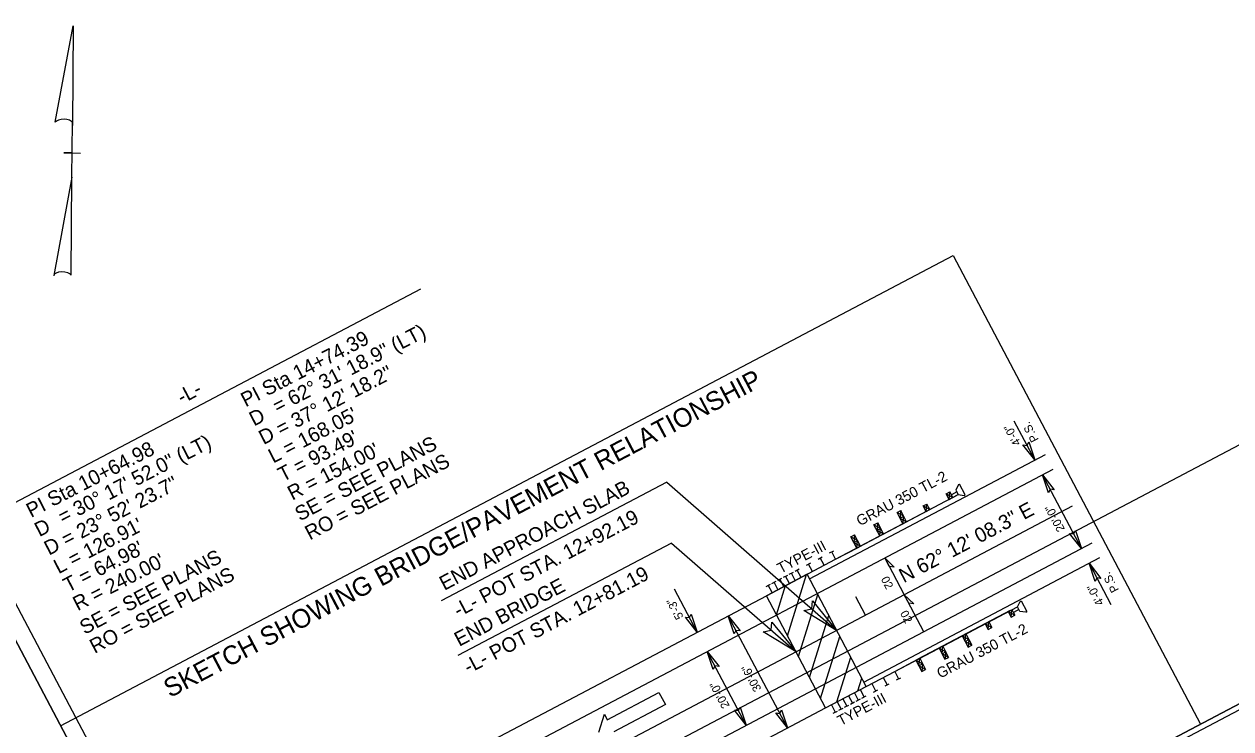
# Model space of a CAD drawing. Extents: x 1380651 to 1383136, y 594581 to 596344.
# Drawn here: x 1381162 to 1381741, y 594902 to 595240 of the extents above; entities that cross this region are included whole.
import ezdxf

# ---------------------------------------------------------------- set-up
doc = ezdxf.new("R2010")
doc.units = 0
for name, color, linetype in [('Default', 7, 'Continuous'), ('Prop Approach Slab', 7, 'Continuous'), ('Prop Approach Slab Hatching', 7, 'Continuous'), ('Prop DGN Element Guardrail', 7, 'Continuous'), ('Prop Dimension', 7, 'Continuous'), ('Prop EOT', 7, 'Continuous'), ('Prop Guardrail', 7, 'Continuous'), ('Prop Guardrail Anchor Unit CELL', 7, 'Continuous'), ('Prop Horizontal Alignment', 7, 'Continuous'), ('Prop Horizontal Alignment Curve and Spiral Data', 7, 'Continuous'), ('Prop Horizontal Alignment Direction Label', 7, 'Continuous'), ('Prop Horizontal Alignment Station Label', 7, 'Continuous'), ('Prop Horizontal Alignment Tick Small', 7, 'Continuous'), ('Prop Lane Arrow CELL', 7, 'Continuous'), ('Prop North Arrow for Plan Sheets CELL', 7, 'Continuous'), ('Prop Paved Shoulder', 7, 'Continuous'), ('Prop Roadway Bridge', 7, 'Continuous'), ('Prop Structure Anchor Unit CELL', 7, 'Continuous'), ('Prop Superelevation  Arrow CELL', 7, 'Continuous'), ('Prop Superelevation Label', 7, 'Continuous'), ('Prop Terminator CELL', 7, 'Continuous'), ('Sheet Block Revision CELL', 7, 'Continuous'), ('Sheet Clip Boundary CELL', 7, 'Continuous'), ('Sheet Layout Plan Border', 7, 'Continuous'), ('Sheet Plan CELL', 7, 'Continuous'), ('Sheet Plot Border Inside CELL', 7, 'Continuous')]:
    doc.layers.add(name, color=color, linetype=linetype)

msp = doc.modelspace()

# ---------------------------------------------------------------- linework, layer by layer
at = {"layer": 'Prop Approach Slab'}
for p, q in [((1381537.57, 594976.49), (1381518.11, 594966.23)), ((1381565.94, 594922.68), (1381537.57, 594976.49)), ((1381546.48, 594912.42), (1381518.11, 594966.23)), ((1381546.48, 594912.42), (1381565.94, 594922.68))]:
    msp.add_line(p, q, dxfattribs=at)
at = {"layer": 'Prop Approach Slab Hatching'}
for p, q in [((1381528.24, 594947.02), (1381537.32, 594976.37)), ((1381522.96, 594957.03), (1381527.32, 594971.09)), ((1381533.51, 594937.01), (1381542.71, 594966.73)), ((1381538.79, 594927), (1381547.99, 594956.72)), ((1381544.07, 594916.99), (1381553.27, 594946.71)), ((1381551.91, 594915.29), (1381558.54, 594936.71)), ((1381561.92, 594920.56), (1381563.82, 594926.7))]:
    msp.add_line(p, q, dxfattribs=at)
at = {"layer": 'Prop DGN Element Guardrail'}
for p, q in [((1381551.28, 594983.72), (1381610.04, 595014.73)), ((1381518.11, 594966.23), (1381551.28, 594983.72)), ((1381579.65, 594929.91), (1381638.44, 594960.87)), ((1381546.48, 594912.42), (1381579.65, 594929.91))]:
    msp.add_line(p, q, dxfattribs=at)
at = {"layer": 'Prop Dimension'}
for p, q in [((1381646.73, 595031.31), (1381636.9, 595049.96)), ((1381669.12, 594988.85), (1381650.46, 595024.24)), ((1381672.85, 594981.77), (1381683.3, 594961.94)), ((1381484.88, 594948.72), (1381474.02, 594969.33)), ((1381528.21, 594902.79), (1381499.84, 594956.6)), ((1381508.39, 594904.12), (1381489.74, 594939.5))]:
    msp.add_line(p, q, dxfattribs=at)
at = {"layer": 'Prop EOT'}
for p, q in [((1381247.91, 594812.01), (1381655.59, 595026.94)), ((1381266.56, 594776.63), (1381674.25, 594991.56))]:
    msp.add_line(p, q, dxfattribs=at)
at = {"layer": 'Prop Guardrail'}
for p, q in [((1381551.28, 594983.72), (1381562.34, 594989.55)), ((1381579.65, 594929.91), (1381590.71, 594935.74))]:
    msp.add_line(p, q, dxfattribs=at)
at = {"layer": 'Prop Guardrail Anchor Unit CELL'}
for p, q in [((1381610.18, 595019.51), (1381608.9, 595016.9)), ((1381610.18, 595019.51), (1381610.72, 595019.79)), ((1381613.47, 595014.6), (1381610.72, 595019.79)), ((1381606.57, 595012.87), (1381562.34, 594989.55)), ((1381604.26, 595015.09), (1381606.03, 595016.02)), ((1381605.68, 595012.4), (1381604.26, 595015.09)), ((1381604.27, 595015.09), (1381607.45, 595013.34)), ((1381605.68, 595012.4), (1381606.04, 595016.02)), ((1381605.68, 595012.4), (1381607.45, 595013.34)), ((1381607.45, 595013.34), (1381606.03, 595016.02)), ((1381609.37, 595016), (1381606.77, 595014.63)), ((1381607.44, 595013.35), (1381610.04, 595014.73)), ((1381608.9, 595016.9), (1381610.04, 595014.73)), ((1381610.04, 595014.73), (1381612.92, 595014.31)), ((1381612.92, 595014.31), (1381613.47, 595014.6)), ((1381580.73, 595006.11), (1381582.5, 595007.05)), ((1381582.5, 595007.05), (1381582.15, 595003.43)), ((1381585.34, 595001.68), (1381582.5, 595007.05)), ((1381593.21, 595009.26), (1381594.98, 595010.19)), ((1381594.62, 595006.57), (1381593.21, 595009.26)), ((1381593.21, 595009.26), (1381596.39, 595007.51)), ((1381594.62, 595006.57), (1381594.98, 595010.19)), ((1381594.62, 595006.57), (1381596.39, 595007.51)), ((1381596.39, 595007.51), (1381594.98, 595010.19)), ((1381569.68, 595000.29), (1381571.45, 595001.22)), ((1381571.45, 595001.22), (1381571.09, 594997.6)), ((1381574.28, 594995.85), (1381571.45, 595001.22)), ((1381583.57, 595000.74), (1381580.73, 595006.11)), ((1381583.92, 595004.36), (1381580.73, 595006.11)), ((1381582.15, 595003.43), (1381583.92, 595004.36)), ((1381582.15, 595003.43), (1381585.34, 595001.68)), ((1381583.57, 595000.74), (1381583.92, 595004.36)), ((1381583.57, 595000.74), (1381585.34, 595001.68)), ((1381558.62, 594994.46), (1381560.39, 594995.39)), ((1381560.39, 594995.39), (1381560.04, 594991.77)), ((1381563.22, 594990.02), (1381560.39, 594995.39)), ((1381572.51, 594994.92), (1381569.68, 595000.29)), ((1381572.86, 594998.53), (1381569.68, 595000.29)), ((1381571.09, 594997.6), (1381572.86, 594998.53)), ((1381571.09, 594997.6), (1381574.28, 594995.85)), ((1381572.51, 594994.92), (1381572.86, 594998.53)), ((1381572.51, 594994.92), (1381574.28, 594995.85)), ((1381561.45, 594989.09), (1381558.62, 594994.46)), ((1381561.81, 594992.71), (1381558.62, 594994.46)), ((1381560.04, 594991.77), (1381561.81, 594992.71)), ((1381560.04, 594991.77), (1381563.22, 594990.02)), ((1381561.45, 594989.09), (1381561.81, 594992.71)), ((1381561.45, 594989.09), (1381563.22, 594990.02)), ((1381635.83, 594959.51), (1381638.44, 594960.87)), ((1381639.57, 594958.71), (1381638.43, 594960.87)), ((1381638.44, 594960.87), (1381639.72, 594963.49)), ((1381639.72, 594963.49), (1381640.26, 594963.78)), ((1381640.26, 594963.78), (1381643, 594958.57)), ((1381634.94, 594959.06), (1381590.71, 594935.74)), ((1381634.05, 594958.59), (1381635.82, 594959.52)), ((1381634.05, 594958.59), (1381635.47, 594955.9)), ((1381634.05, 594958.59), (1381637.24, 594956.84)), ((1381635.47, 594955.9), (1381635.82, 594959.52)), ((1381635.47, 594955.9), (1381637.24, 594956.84)), ((1381635.82, 594959.52), (1381637.24, 594956.84)), ((1381639.1, 594959.6), (1381636.5, 594958.23)), ((1381642.45, 594958.28), (1381639.57, 594958.71)), ((1381642.45, 594958.28), (1381643, 594958.57)), ((1381622.99, 594952.76), (1381624.76, 594953.69)), ((1381622.99, 594952.76), (1381624.41, 594950.07)), ((1381622.99, 594952.76), (1381626.18, 594951.01)), ((1381624.41, 594950.07), (1381624.76, 594953.69)), ((1381624.41, 594950.07), (1381626.18, 594951.01)), ((1381624.76, 594953.69), (1381626.18, 594951.01)), ((1381611.94, 594946.93), (1381613.71, 594947.86)), ((1381611.94, 594946.93), (1381614.77, 594941.56)), ((1381611.94, 594946.93), (1381615.12, 594945.18)), ((1381613.35, 594944.25), (1381613.71, 594947.86)), ((1381613.35, 594944.25), (1381615.12, 594945.18)), ((1381616.54, 594942.49), (1381613.35, 594944.25)), ((1381613.71, 594947.86), (1381616.54, 594942.49)), ((1381615.12, 594945.18), (1381614.77, 594941.56)), ((1381600.88, 594941.1), (1381602.65, 594942.03)), ((1381600.88, 594941.1), (1381603.71, 594935.73)), ((1381600.88, 594941.1), (1381604.06, 594939.35)), ((1381602.3, 594938.42), (1381602.65, 594942.03)), ((1381602.3, 594938.42), (1381604.06, 594939.35)), ((1381605.48, 594936.66), (1381602.3, 594938.42)), ((1381602.65, 594942.03), (1381605.48, 594936.66)), ((1381604.06, 594939.35), (1381603.71, 594935.73)), ((1381614.77, 594941.56), (1381616.54, 594942.49)), ((1381589.82, 594935.27), (1381591.59, 594936.21)), ((1381589.82, 594935.27), (1381592.65, 594929.9)), ((1381589.82, 594935.27), (1381593.01, 594933.52)), ((1381591.24, 594932.59), (1381591.59, 594936.21)), ((1381591.24, 594932.59), (1381593.01, 594933.52)), ((1381594.42, 594930.83), (1381591.24, 594932.59)), ((1381591.59, 594936.21), (1381594.42, 594930.83)), ((1381593.01, 594933.52), (1381592.65, 594929.9)), ((1381603.71, 594935.73), (1381605.48, 594936.66)), ((1381592.65, 594929.9), (1381594.42, 594930.83))]:
    msp.add_line(p, q, dxfattribs=at)
at = {"layer": 'Prop Horizontal Alignment'}
msp.add_line((1381259.34, 594795.43), (1381664.92, 595009.25), dxfattribs=at)
at = {"layer": 'Prop Horizontal Alignment Curve and Spiral Data'}
msp.add_line((1381154.62, 595009.14), (1381352.46, 595113.44), dxfattribs=at)
at = {"layer": 'Prop Horizontal Alignment Station Label'}
for p, q in [((1381470.29, 595020.72), (1381362.17, 594963.72)), ((1381470.29, 595020.72), (1381551.75, 594949.59)), ((1381472.59, 594991.46), (1381370.22, 594937.49)), ((1381472.59, 594991.46), (1381532.29, 594939.33))]:
    msp.add_line(p, q, dxfattribs=at)
at = {"layer": 'Prop Horizontal Alignment Tick Small'}
msp.add_line((1381565.57, 594956.87), (1381560.91, 594965.72), dxfattribs=at)
at = {"layer": 'Prop Lane Arrow CELL'}
for p, q in [((1381441.81, 594906.77), (1381466.58, 594919.83)), ((1381466.58, 594919.83), (1381469.66, 594913.99)), ((1381469.66, 594913.99), (1381444.89, 594900.93)), ((1381437.82, 594900.82), (1381440.41, 594909.42)), ((1381440.41, 594909.42), (1381441.81, 594906.77))]:
    msp.add_line(p, q, dxfattribs=at)
at = {"layer": 'Prop North Arrow for Plan Sheets CELL'}
for p, q in [((1381177.14, 595193.28), (1381185.75, 595239.55)), ((1381185.8, 595239.55), (1381185.38, 595191.76)), ((1381185.8, 595239.55), (1381185.75, 595239.55)), ((1381185.8, 595239.55), (1381185.75, 595239.55)), ((1381185.16, 595166.96), (1381185.39, 595193.16)), ((1381185.38, 595191.76), (1381185.39, 595193.11)), ((1381181.26, 595178.59), (1381181.21, 595178.59)), ((1381184.81, 595178.56), (1381181.26, 595178.59)), ((1381181.31, 595178.59), (1381189.31, 595178.52)), ((1381185.16, 595166.96), (1381176.39, 595119.78)), ((1381184.79, 595119.91), (1381185.16, 595166.96))]:
    msp.add_line(p, q, dxfattribs=at)
for centre, start_param, end_param in [((1381181.27, 595192.75), 0.216388, 2.908219), ((1381180.62, 595119.58), 0.201328, 3.141593)]:
    msp.add_ellipse(centre, major_axis=(4.23, -0.07), ratio=0.461098, start_param=start_param, end_param=end_param, dxfattribs=at)
at = {"layer": 'Prop Paved Shoulder'}
for p, q in [((1381538.69, 594974.36), (1381651.86, 595034.02)), ((1381564.81, 594924.82), (1381677.98, 594984.48))]:
    msp.add_line(p, q, dxfattribs=at)
at = {"layer": 'Prop Roadway Bridge'}
for p, q in [((1381345.82, 594875.41), (1381518.11, 594966.23)), ((1381374.19, 594821.59), (1381546.48, 594912.42))]:
    msp.add_line(p, q, dxfattribs=at)
at = {"layer": 'Prop Structure Anchor Unit CELL'}
for p, q in [((1381518.11, 594966.23), (1381551.28, 594983.72)), ((1381542.87, 594983.81), (1381544.9, 594984.88)), ((1381545.75, 594980.81), (1381543.88, 594984.35)), ((1381548.4, 594986.73), (1381550.43, 594987.8)), ((1381551.28, 594983.72), (1381549.41, 594987.26)), ((1381529.05, 594976.53), (1381531.08, 594977.59)), ((1381531.81, 594977.98), (1381533.84, 594979.05)), ((1381534.69, 594974.98), (1381532.83, 594978.52)), ((1381537.34, 594980.9), (1381539.37, 594981.97)), ((1381540.22, 594977.89), (1381538.36, 594981.43)), ((1381517.99, 594970.7), (1381520.02, 594971.76)), ((1381520.76, 594972.15), (1381522.78, 594973.22)), ((1381523.63, 594969.15), (1381521.77, 594972.69)), ((1381523.52, 594973.61), (1381525.55, 594974.68)), ((1381526.4, 594970.61), (1381524.53, 594974.15)), ((1381526.28, 594975.07), (1381528.31, 594976.14)), ((1381529.16, 594972.06), (1381527.3, 594975.6)), ((1381531.93, 594973.52), (1381530.06, 594977.06)), ((1381520.87, 594967.69), (1381519.01, 594971.23)), ((1381546.48, 594912.42), (1381579.65, 594929.91)), ((1381574.12, 594926.99), (1381575.98, 594923.46)), ((1381579.65, 594929.91), (1381581.51, 594926.37)), ((1381580.5, 594925.84), (1381582.53, 594926.91)), ((1381560.3, 594919.71), (1381562.16, 594916.17)), ((1381563.06, 594921.17), (1381564.93, 594917.63)), ((1381568.59, 594924.08), (1381570.46, 594920.54)), ((1381569.44, 594920.01), (1381571.47, 594921.08)), ((1381574.97, 594922.92), (1381577, 594923.99)), ((1381549.24, 594913.88), (1381551.11, 594910.34)), ((1381552, 594915.34), (1381553.87, 594911.8)), ((1381554.77, 594916.79), (1381556.63, 594913.26)), ((1381557.53, 594918.25), (1381559.4, 594914.71)), ((1381558.39, 594914.18), (1381560.41, 594915.25)), ((1381561.15, 594915.64), (1381563.18, 594916.7)), ((1381563.91, 594917.09), (1381565.94, 594918.16)), ((1381550.09, 594909.81), (1381552.12, 594910.87)), ((1381552.86, 594911.26), (1381554.88, 594912.33)), ((1381555.62, 594912.72), (1381557.65, 594913.79))]:
    msp.add_line(p, q, dxfattribs=at)
at = {"layer": 'Prop Superelevation  Arrow CELL'}
for points in [[(1381574.83, 594984.36), (1381579.4, 594979.99), (1381576.99, 594980.27)], [(1381584.16, 594966.67), (1381588.72, 594962.3), (1381586.31, 594962.58)]]:
    msp.add_lwpolyline(points, close=True, dxfattribs=at)
at = {"layer": 'Prop Superelevation Label'}
for p, q in [((1381574.83, 594984.36), (1381584.16, 594966.67)), ((1381584.16, 594966.67), (1381593.48, 594948.98))]:
    msp.add_line(p, q, dxfattribs=at)
at = {"layer": 'Prop Terminator CELL'}
for points in [[(1381643.91, 595040), (1381646.73, 595031.31), (1381641.1, 595038.57), (1381643.05, 595038.3)], [(1381653.29, 595015.55), (1381650.46, 595024.24), (1381656.1, 595016.98), (1381654.15, 595017.25)], [(1381666.29, 594997.54), (1381669.12, 594988.85), (1381663.48, 594996.11), (1381665.43, 594995.84)], [(1381675.67, 594973.09), (1381672.85, 594981.77), (1381678.48, 594974.52), (1381676.53, 594974.79)], [(1381540.23, 594963.76), (1381551.75, 594949.59), (1381536.01, 594959.08), (1381539.85, 594959.98)], [(1381482.06, 594957.4), (1381484.88, 594948.72), (1381479.25, 594955.98), (1381481.2, 594955.71)], [(1381502.66, 594947.92), (1381499.84, 594956.6), (1381505.47, 594949.34), (1381503.52, 594949.61)], [(1381520.78, 594953.51), (1381532.29, 594939.33), (1381516.56, 594948.84), (1381520.4, 594949.73)], [(1381492.57, 594930.82), (1381489.74, 594939.5), (1381495.38, 594932.25), (1381493.42, 594932.52)], [(1381505.57, 594912.81), (1381508.39, 594904.12), (1381502.76, 594911.38), (1381504.71, 594911.11)], [(1381525.38, 594911.47), (1381528.21, 594902.79), (1381522.57, 594910.05), (1381524.52, 594909.78)]]:
    msp.add_lwpolyline(points, close=True, dxfattribs=at)
at = {"layer": 'Sheet Block Revision CELL'}
msp.add_lwpolyline([(1381144.43, 594840.95), (1380775.71, 595540.36), (1380829.25, 595568.61), (1381197.97, 594869.2)], close=True, dxfattribs=at)
at = {"layer": 'Sheet Clip Boundary CELL'}
msp.add_lwpolyline([(1381254.23, 594780.01), (1382566.26, 595471.7), (1382154.39, 596252.97), (1381978.55, 596160.27), (1381909.21, 596291.79), (1380773.01, 595692.8)], close=True, dxfattribs=at)
at = {"layer": 'Sheet Layout Plan Border'}
msp.add_lwpolyline([(1381298.21, 594679), (1382625.14, 595378.54), (1382205.45, 596174.64), (1382028.49, 596081.35), (1381958.53, 596214.06), (1380808.55, 595607.8)], close=True, dxfattribs=at)
at = {"layer": 'Sheet Plan CELL'}
for p, q in [((1381179.73, 594903.77), (1381607.69, 595129.38)), ((1381607.69, 595129.38), (1381726.18, 594904.62))]:
    msp.add_line(p, q, dxfattribs=at)
for points in [[(1382135.49, 596307.38), (1380808.56, 595607.84), (1381298.23, 594679.01), (1382625.14, 595378.54)], [(1381298.23, 594679.01), (1380808.55, 595607.8), (1381958.5, 596214.09), (1382028.49, 596081.35), (1382205.45, 596174.63), (1382625.14, 595378.54)]]:
    msp.add_lwpolyline(points, close=True, dxfattribs=at)
at = {"layer": 'Sheet Plot Border Inside CELL'}
msp.add_lwpolyline([(1381163.62, 594605.21), (1382637.35, 595382.15), (1382145.37, 596315.4), (1380671.62, 595538.46)], close=True, dxfattribs=at)

# ---------------------------------------------------------------- texts
at = {"layer": 'Default'}
for p in [(1381648.78, 595041.1), (1381687.24, 594969.02)]:
    msp.add_text('P.S.', height=4, rotation=117.7977, dxfattribs=at).set_placement(p)
at = {"layer": 'Prop Dimension'}
for s, p in [('4\'-0"', (1381640.24, 595039.36)), ('20\'-0"', (1381661.31, 594998.16)), ('4\'-0"', (1381680.07, 594962.75)), ('5\'-3"', (1381478.48, 594956.06)), ('30\'-6"', (1381515.84, 594921.47)), ('20\'-0"', (1381500.59, 594913.43))]:
    msp.add_text(s, height=4, rotation=117.7977, dxfattribs=at).set_placement(p)
at = {"layer": 'Prop Guardrail Anchor Unit CELL'}
for p in [(1381562.89, 594999.5), (1381601.43, 594926.39)]:
    msp.add_text('GRAU 350 TL-2', height=5, rotation=27.7977, dxfattribs=at).set_placement(p)
at = {"layer": 'Prop Horizontal Alignment Curve and Spiral Data'}
for s, rotation, p in [('= 62%%d 31\' 18.9" (LT)', 27.33569, (1381283.7, 595053.49)), ('PI Sta 14+74.39', 27.33569, (1381268.43, 595056.52)), ('D = 37%%d 12\' 18.2"', 27.33569, (1381277.01, 595038.45)), ('-L-', 27.7977, (1381237.88, 595057.98)), ('D', 27.33569, (1381272.42, 595047.33)), ("L = 168.05'", 27.33569, (1381281.61, 595029.56)), ('= 30%%d 17\' 52.0" (LT)', 27.32967, (1381180.8, 595000.44)), ("T = 93.49'", 27.33569, (1381286.2, 595020.68)), ('SE = SEE PLANS', 27.89636, (1381294.42, 595001.79)), ('PI Sta 10+64.98', 27.32967, (1381165.53, 595003.47)), ("R = 154.00'", 27.33569, (1381290.79, 595011.8)), ('RO = SEE PLANS', 27.89636, (1381299.21, 594992.7)), ('D = 23%%d 52\' 23.7"', 27.32967, (1381174.11, 594985.4)), ('D', 27.32967, (1381169.52, 594994.28)), ("L = 126.91'", 27.32967, (1381178.7, 594976.51)), ("T = 64.98'", 27.32967, (1381183.29, 594967.63)), ("R = 240.00'", 27.32967, (1381187.88, 594958.75)), ('SE = SEE PLANS', 27.89636, (1381191.22, 594947.39)), ('RO = SEE PLANS', 27.89636, (1381196.01, 594938.3))]:
    msp.add_text(s, height=7, rotation=rotation, dxfattribs=at).set_placement(p)
at = {"layer": 'Prop Horizontal Alignment Direction Label'}
msp.add_text('N 62%%d 12\' 08.3" E', height=7, rotation=27.7977, dxfattribs=at).set_placement((1381583.99, 594972.14))
at = {"layer": 'Prop Horizontal Alignment Station Label'}
for s, height, p in [('SKETCH SHOWING BRIDGE/PAVEMENT RELATIONSHIP', 9, (1381232.16, 594917.09)), ('END APPROACH SLAB', 7, (1381363.66, 594968.52)), ('-L- POT STA. 12+92.19', 7, (1381370.42, 594955.7)), ('-L- POT STA. 12+81.19', 7, (1381375.24, 594928.56)), ('END BRIDGE', 7, (1381370.8, 594941.67))]:
    msp.add_text(s, height=height, rotation=27.7977, dxfattribs=at).set_placement(p)
at = {"layer": 'Prop Structure Anchor Unit CELL'}
for p in [(1381524.94, 594976.77), (1381553.78, 594903.68)]:
    msp.add_text('TYPE-III', height=5, rotation=27.7977, dxfattribs=at).set_placement(p)
at = {"layer": 'Prop Superelevation Label'}
for p in [(1381572.86, 594974.19), (1381582.02, 594957.83)]:
    msp.add_text('02', height=4, rotation=297.7977, dxfattribs=at).set_placement(p)

doc.saveas('drawing.dxf')
